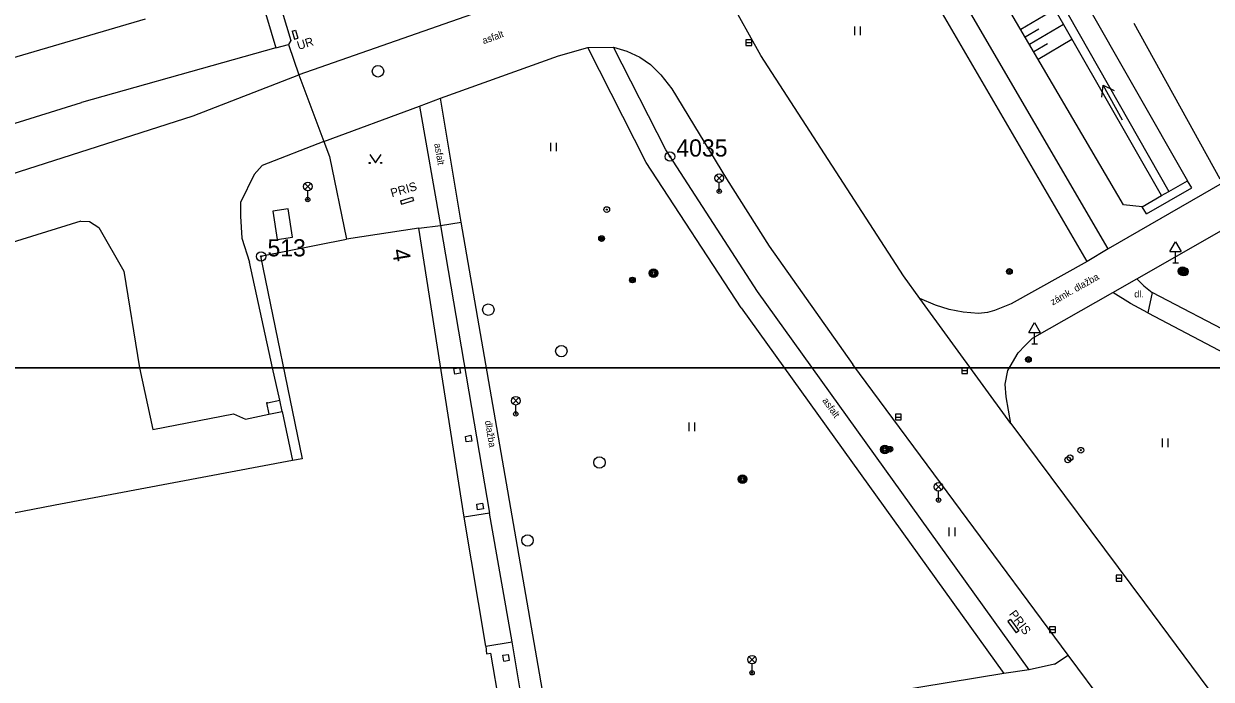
# Model space of a CAD drawing. Extents: x -493753 to -49290, y -1127285 to -112654.
# Drawn here: x -493511.1 to -493407.4, y -1127027.2 to -1126970 of the extents above; entities that cross this region are included whole.
import ezdxf

# ---------------------------------------------------------------- set-up
doc = ezdxf.new("R2010")
doc.units = 0
for name, color, linetype in [('Vrstva 10', 7, 'Continuous'), ('Vrstva 11', 7, 'Continuous'), ('Vrstva 14', 7, 'Continuous'), ('Vrstva 15', 7, 'Continuous'), ('Vrstva 24', 7, 'Continuous'), ('Vrstva 25', 7, 'Continuous'), ('Vrstva 27', 7, 'Continuous'), ('Vrstva 28', 7, 'Continuous'), ('Vrstva 31', 7, 'Continuous'), ('Vrstva 33', 7, 'Continuous'), ('Vrstva 34', 7, 'Continuous'), ('Vrstva 36', 7, 'Continuous'), ('Vrstva 40', 7, 'Continuous'), ('Vrstva 42', 7, 'Continuous'), ('Vrstva 44', 7, 'Continuous'), ('Vrstva 45', 7, 'Continuous'), ('Vrstva 5', 7, 'Continuous'), ('Vrstva 60', 7, 'Continuous'), ('Vrstva 63', 7, 'Continuous'), ('Vrstva 7', 7, 'Continuous'), ('Vrstva 8', 7, 'Continuous')]:
    doc.layers.add(name, color=color, linetype=linetype)

msp = doc.modelspace()

# ---------------------------------------------------------------- linework, layer by layer
at = {"layer": 'Vrstva 10'}
for p, q in [((-493416.42, -1126989.62), (-493448.94, -1126933.89)), ((-493418.27, -1126990.72), (-493451.01, -1126934.56)), ((-493446.75, -1126972.75), (-493453.23, -1126961.09)), ((-493464.93, -1126966.68), (-493487.06, -1126974.42)), ((-493464.41, -1126972.76), (-493461.84, -1126972.04)), ((-493461.84, -1126972.04), (-493459.59, -1126972.03)), ((-493456.75, -1126982.08), (-493461.84, -1126972.04)), ((-493455.02, -1126980.96), (-493459.59, -1126972.03)), ((-493474.71, -1126976.48), (-493464.41, -1126972.76)), ((-493434.29, -1126991.96), (-493446.75, -1126972.75)), ((-493454.52, -1126975.65), (-493449.75, -1126983.49)), ((-493476.53, -1126977.16), (-493474.71, -1126976.48)), ((-493472.89, -1126987.28), (-493474.71, -1126976.48)), ((-493484.89, -1126980.24), (-493476.53, -1126977.16)), ((-493476.53, -1126977.16), (-493474.69, -1126987.58)), ((-493447.03, -1126993.34), (-493455.02, -1126980.96)), ((-493448.45, -1126994.76), (-493456.75, -1126982.08)), ((-493449.75, -1126983.49), (-493446.02, -1126989.37)), ((-493406.46, -1126983.89), (-493416.42, -1126989.62)), ((-493409.13, -1126984.29), (-493409.5, -1126983.67)), ((-493413.09, -1126986.57), (-493409.13, -1126984.29)), ((-493413.09, -1126986.57), (-493413.46, -1126985.95)), ((-493413.91, -1126992.22), (-493404.75, -1126986.99)), ((-493464.92, -1127033.14), (-493472.89, -1126987.28)), ((-493446.02, -1126989.37), (-493438.7, -1126999.69)), ((-493418.27, -1126990.72), (-493424.88, -1126994.4)), ((-493432.85, -1126993.93), (-493434.29, -1126991.96)), ((-493423.31, -1127026.33), (-493447.03, -1126993.34)), ((-493424.93, -1127004.86), (-493432.85, -1126993.93)), ((-493423.04, -1126997.41), (-493416.01, -1126993.41)), ((-493391.92, -1127004.22), (-493412.57, -1126993.41)), ((-493448.45, -1126994.76), (-493425.54, -1127026.66)), ((-493412.95, -1126995.18), (-493392.82, -1127005.8)), ((-493473.53, -1127000.06), (-493473.04, -1126999.98)), ((-493473.45, -1127000.55), (-493473.53, -1127000.06)), ((-493472.95, -1127000.47), (-493473.45, -1127000.55)), ((-493473.04, -1126999.98), (-493472.95, -1127000.47)), ((-493419.91, -1127025.06), (-493438.7, -1126999.69)), ((-493424.93, -1127004.86), (-493413.25, -1127020.49)), ((-493472.53, -1127005.97), (-493472.04, -1127005.88)), ((-493472.45, -1127006.46), (-493472.53, -1127005.97)), ((-493471.96, -1127006.38), (-493472.45, -1127006.46)), ((-493472.04, -1127005.88), (-493471.96, -1127006.38)), ((-493471.54, -1127011.88), (-493471.05, -1127011.8)), ((-493471.46, -1127012.37), (-493471.54, -1127011.88)), ((-493471.05, -1127011.8), (-493470.96, -1127012.29)), ((-493470.96, -1127012.29), (-493471.46, -1127012.37)), ((-493468.45, -1127023.89), (-493470.41, -1127012.67)), ((-493469.26, -1127025.07), (-493468.76, -1127024.99)), ((-493469.18, -1127025.57), (-493469.26, -1127025.07)), ((-493469.18, -1127025.57), (-493468.69, -1127025.49)), ((-493468.69, -1127025.49), (-493468.76, -1127024.99)), ((-493421.12, -1127025.84), (-493419.91, -1127025.06)), ((-493411.78, -1127035.96), (-493419.91, -1127025.06)), ((-493423.31, -1127026.33), (-493425.54, -1127026.66)), ((-493421.12, -1127025.84), (-493423.31, -1127026.33))]:
    msp.add_line(p, q, dxfattribs=at)
for points in [[(-493459.59, -1126972.03), (-493458.45, -1126972.37), (-493457.31, -1126972.88), (-493456.37, -1126973.52), (-493455.47, -1126974.42), (-493454.52, -1126975.65)], [(-493413.46, -1126985.95), (-493411.76, -1126984.97), (-493411.12, -1126984.6), (-493409.5, -1126983.67)], [(-493413.91, -1126992.22), (-493413.32, -1126992.83), (-493412.57, -1126993.41)], [(-493427.75, -1126995.25), (-493429.09, -1126995.13), (-493430.29, -1126994.89), (-493431.48, -1126994.53), (-493432.85, -1126993.93)], [(-493424.88, -1126994.4), (-493426.35, -1126995), (-493426.97, -1126995.17), (-493427.75, -1126995.25)], [(-493412.95, -1126995.18), (-493414.47, -1126994.37), (-493416.01, -1126993.41)], [(-493425.19, -1127000.22), (-493424.27, -1126998.69), (-493423.67, -1126998.03), (-493423.04, -1126997.41)], [(-493424.93, -1127004.86), (-493425.33, -1127002.51), (-493425.41, -1127001.41), (-493425.19, -1127000.22)], [(-493413.25, -1127020.49), (-493403.62, -1127033.47)], [(-493425.54, -1127026.66), (-493464.92, -1127033.14), (-493466.83, -1127033.46)]]:
    msp.add_lwpolyline(points, dxfattribs=at)
at = {"layer": 'Vrstva 11'}
for p, q in [((-493474.69, -1126987.58), (-493472.89, -1126987.28)), ((-493416.42, -1126989.62), (-493418.27, -1126990.72)), ((-493416.01, -1126993.41), (-493413.91, -1126992.22)), ((-493412.57, -1126993.41), (-493412.95, -1126995.18))]:
    msp.add_line(p, q, dxfattribs=at)
for points in [[(-493524.38, -1126986.98), (-493496.3, -1126978.01), (-493487.06, -1126974.42)], [(-493536.04, -1126986.19), (-493506.03, -1126976.85)], [(-493484.89, -1126980.24), (-493490.28, -1126982.35), (-493490.98, -1126983.14), (-493492.16, -1126985.58), (-493492.16, -1126986.76), (-493492.03, -1126988.68), (-493491.36, -1126990.78)], [(-493488, -1126986.12), (-493489.33, -1126986.33)], [(-493489.33, -1126986.33), (-493488.95, -1126988.8)], [(-493487.62, -1126988.59), (-493488, -1126986.12)], [(-493506.09, -1126987.19), (-493523.25, -1126992.52)], [(-493506.09, -1126987.19), (-493505.35, -1126987.23), (-493504.52, -1126987.76), (-493502.34, -1126991.55), (-493500.98, -1127000)], [(-493488.95, -1126988.8), (-493487.62, -1126988.59)], [(-493489.36, -1127000), (-493491.36, -1126990.78)], [(-493500.98, -1127000), (-493499.8, -1127005.36), (-493492.77, -1127004.02), (-493491.71, -1127004.47), (-493489.69, -1127004.03)], [(-493488.74, -1127002.81), (-493489.36, -1127000)], [(-493489.81, -1127003.04), (-493489.9, -1127003.06)], [(-493489.9, -1127003.06), (-493489.69, -1127004.03)], [(-493489.81, -1127003.04), (-493488.74, -1127002.81)], [(-493488.53, -1127003.79), (-493488.74, -1127002.81)], [(-493489.69, -1127004.03), (-493488.53, -1127003.79)], [(-493488.53, -1127003.79), (-493487.63, -1127008.08)], [(-493487.63, -1127008.08), (-493508.33, -1127011.97)], [(-493486.79, -1127007.92), (-493487.63, -1127008.08)], [(-493508.33, -1127011.97), (-493523.38, -1127014.87)]]:
    msp.add_lwpolyline(points, dxfattribs=at)
at = {"layer": 'Vrstva 14'}
for p, q in [((-493441.57, -1126927.45), (-493409.5, -1126983.67)), ((-493411.76, -1126984.97), (-493444.16, -1126928.37)), ((-493443.13, -1126928.34), (-493411.12, -1126984.6)), ((-493415.09, -1126985.77), (-493447.31, -1126930.76)), ((-493413.46, -1126985.95), (-493415.09, -1126985.77))]:
    msp.add_line(p, q, dxfattribs=at)
at = {"layer": 'Vrstva 15'}
for p, q in [((-493424.06, -1126970.46), (-493421.07, -1126968.71)), ((-493423.68, -1126971.11), (-493422.48, -1126970.41)), ((-493423.3, -1126971.76), (-493420.32, -1126970.01)), ((-493422.54, -1126973.05), (-493419.58, -1126971.31)), ((-493422.92, -1126972.4), (-493421.73, -1126971.71))]:
    msp.add_line(p, q, dxfattribs=at)
at = {"layer": 'Vrstva 24'}
for p, q in [((-493487.66, -1126970.61), (-493487.37, -1126970.52)), ((-493487.37, -1126970.52), (-493487.15, -1126971.23)), ((-493487.66, -1126970.61), (-493487.44, -1126971.32)), ((-493487.44, -1126971.32), (-493487.15, -1126971.23)), ((-493478.18, -1126985.41), (-493477.15, -1126985.11)), ((-493478.18, -1126985.41), (-493478.1, -1126985.7)), ((-493478.1, -1126985.7), (-493477.07, -1126985.4)), ((-493477.15, -1126985.11), (-493477.07, -1126985.4)), ((-493424.95, -1127021.94), (-493425.19, -1127022.12)), ((-493425.19, -1127022.12), (-493424.45, -1127023.11)), ((-493424.95, -1127021.94), (-493424.21, -1127022.93)), ((-493424.21, -1127022.93), (-493424.45, -1127023.11))]:
    msp.add_line(p, q, dxfattribs=at)
at = {"layer": 'Vrstva 25'}
for centre, radius in [((-493460.19, -1126986.19), 0.25), ((-493460.19, -1126986.19), 0.05), ((-493460.64, -1126988.72), 0.25), ((-493460.64, -1126988.72), 0.158), ((-493460.64, -1126988.72), 0.05), ((-493457.95, -1126992.33), 0.25), ((-493457.95, -1126992.33), 0.158), ((-493457.95, -1126992.33), 0.05), ((-493425.04, -1126991.58), 0.25), ((-493425.04, -1126991.58), 0.158), ((-493425.04, -1126991.58), 0.05), ((-493423.38, -1126999.26), 0.25), ((-493423.38, -1126999.26), 0.158), ((-493423.38, -1126999.26), 0.05), ((-493435.48, -1127007.1), 0.25), ((-493435.48, -1127007.1), 0.158), ((-493435.48, -1127007.1), 0.05), ((-493418.81, -1127007.18), 0.25), ((-493418.81, -1127007.18), 0.05)]:
    msp.add_circle(centre, radius, dxfattribs=at)
at = {"layer": 'Vrstva 27'}
for p, q in [((-493448.04, -1126971.62), (-493447.54, -1126971.62)), ((-493429.19, -1127000.23), (-493428.69, -1127000.23)), ((-493434.98, -1127004.29), (-493434.48, -1127004.29)), ((-493415.73, -1127018.34), (-493415.23, -1127018.34)), ((-493421.53, -1127022.83), (-493421.03, -1127022.83))]:
    msp.add_line(p, q, dxfattribs=at)
for points in [[(-493448.04, -1126971.87), (-493447.54, -1126971.87), (-493447.54, -1126971.37), (-493448.04, -1126971.37)], [(-493429.19, -1127000.48), (-493428.69, -1127000.48), (-493428.69, -1126999.98), (-493429.19, -1126999.98)], [(-493434.98, -1127004.54), (-493434.48, -1127004.54), (-493434.48, -1127004.04), (-493434.98, -1127004.04)], [(-493415.73, -1127018.59), (-493415.23, -1127018.59), (-493415.23, -1127018.09), (-493415.73, -1127018.09)], [(-493421.53, -1127023.08), (-493421.03, -1127023.08), (-493421.03, -1127022.58), (-493421.53, -1127022.58)]]:
    msp.add_lwpolyline(points, close=True, dxfattribs=at)
for centre in [(-493480.16, -1126974.12), (-493470.53, -1126994.92), (-493464.15, -1126998.53), (-493460.83, -1127008.25), (-493467.1, -1127015.05)]:
    msp.add_circle(centre, 0.5, dxfattribs=at)
at = {"layer": 'Vrstva 28'}
for centre in [(-493419.95, -1127008.02), (-493419.75, -1127007.84)]:
    msp.add_circle(centre, 0.25, dxfattribs=at)
at = {"layer": 'Vrstva 31'}
for centre, radius in [((-493409.93, -1126991.55), 0.375), ((-493409.93, -1126991.55), 0.283), ((-493409.82, -1126991.6), 0.375), ((-493456.1, -1126991.73), 0.375), ((-493456.1, -1126991.73), 0.283), ((-493456.1, -1126991.73), 0.224), ((-493456.1, -1126991.73), 0.112), ((-493409.93, -1126991.55), 0.224), ((-493409.82, -1126991.6), 0.283), ((-493409.82, -1126991.6), 0.224), ((-493409.93, -1126991.55), 0.112), ((-493409.82, -1126991.6), 0.112), ((-493435.91, -1127007.12), 0.375), ((-493435.91, -1127007.12), 0.283), ((-493435.91, -1127007.12), 0.224), ((-493435.91, -1127007.12), 0.112), ((-493448.34, -1127009.71), 0.375), ((-493448.34, -1127009.71), 0.283), ((-493448.34, -1127009.71), 0.224), ((-493448.34, -1127009.71), 0.112)]:
    msp.add_circle(centre, radius, dxfattribs=at)
at = {"layer": 'Vrstva 33'}
for p, q in [((-493486.555, -1126983.905), (-493486.025, -1126984.435)), ((-493486.555, -1126984.435), (-493486.025, -1126983.905)), ((-493450.635, -1126983.175), (-493450.105, -1126983.705)), ((-493450.635, -1126983.705), (-493450.105, -1126983.175)), ((-493450.37, -1126984.59), (-493450.37, -1126983.815)), ((-493486.29, -1126985.32), (-493486.29, -1126984.545)), ((-493468.395, -1127002.595), (-493467.865, -1127003.125)), ((-493468.395, -1127003.125), (-493467.865, -1127002.595)), ((-493468.13, -1127004.01), (-493468.13, -1127003.235)), ((-493431.495, -1127010.115), (-493430.965, -1127010.645)), ((-493431.495, -1127010.645), (-493430.965, -1127010.115)), ((-493431.23, -1127011.53), (-493431.23, -1127010.755)), ((-493447.775, -1127025.185), (-493447.245, -1127025.715)), ((-493447.775, -1127025.715), (-493447.245, -1127025.185)), ((-493447.51, -1127026.6), (-493447.51, -1127025.825))]:
    msp.add_line(p, q, dxfattribs=at)
for centre, radius in [((-493486.29, -1126984.17), 0.375), ((-493450.37, -1126983.44), 0.375), ((-493450.37, -1126984.59), 0.19), ((-493450.37, -1126984.59), 0.05), ((-493486.29, -1126985.32), 0.19), ((-493486.29, -1126985.32), 0.05), ((-493468.13, -1127002.86), 0.375), ((-493468.13, -1127004.01), 0.19), ((-493468.13, -1127004.01), 0.05), ((-493431.23, -1127010.38), 0.375), ((-493431.23, -1127011.53), 0.19), ((-493431.23, -1127011.53), 0.05), ((-493447.51, -1127025.45), 0.375), ((-493447.51, -1127026.6), 0.19), ((-493447.51, -1127026.6), 0.05)]:
    msp.add_circle(centre, radius, dxfattribs=at)
at = {"layer": 'Vrstva 34'}
for p, q in [((-493411.04, -1126989.84), (-493410.54, -1126988.99)), ((-493410.54, -1126988.99), (-493410.04, -1126989.84)), ((-493411.04, -1126989.84), (-493410.04, -1126989.84)), ((-493410.54, -1126990.84), (-493410.54, -1126989.84)), ((-493410.79, -1126990.84), (-493410.29, -1126990.84)), ((-493423.35, -1126996.9), (-493422.85, -1126996.05)), ((-493422.85, -1126996.05), (-493422.35, -1126996.9)), ((-493423.35, -1126996.9), (-493422.35, -1126996.9)), ((-493422.85, -1126997.9), (-493422.85, -1126996.9)), ((-493423.1, -1126997.9), (-493422.6, -1126997.9))]:
    msp.add_line(p, q, dxfattribs=at)
at = {"layer": 'Vrstva 36'}
for p, q in [((-493438.53, -1126970.97), (-493438.53, -1126970.22)), ((-493438.03, -1126970.97), (-493438.03, -1126970.22)), ((-493465.08, -1126981.1), (-493465.08, -1126980.35)), ((-493464.58, -1126981.1), (-493464.58, -1126980.35)), ((-493480.88, -1126981.37), (-493480.38, -1126982.12)), ((-493480.38, -1126982.12), (-493479.88, -1126981.37)), ((-493453.01, -1127005.51), (-493453.01, -1127004.76)), ((-493452.51, -1127005.51), (-493452.51, -1127004.76)), ((-493411.68, -1127006.92), (-493411.68, -1127006.17)), ((-493411.18, -1127006.92), (-493411.18, -1127006.17)), ((-493430.29, -1127014.68), (-493430.29, -1127013.93)), ((-493429.79, -1127014.68), (-493429.79, -1127013.93))]:
    msp.add_line(p, q, dxfattribs=at)
for centre in [(-493480.88, -1126982.12), (-493479.88, -1126982.12)]:
    msp.add_circle(centre, 0.05, dxfattribs=at)
at = {"layer": 'Vrstva 45'}
for p, q in [((-493416.975, -1126976.391), (-493416.85, -1126975.33)), ((-493415.161, -1126978.395), (-493416.85, -1126975.33)), ((-493416.85, -1126975.33), (-493415.887, -1126975.792))]:
    msp.add_line(p, q, dxfattribs=at)
at = {"layer": 'Vrstva 5'}
for p, q in [((-493500.47, -1126969.56), (-493517.82, -1126974.66)), ((-493476.59, -1126987.82), (-493482.91, -1126988.76)), ((-493476.59, -1126987.82), (-493474.69, -1126987.58)), ((-493472.64, -1127013.02), (-493476.59, -1126987.82)), ((-493474.69, -1126987.58), (-493470.41, -1127012.67)), ((-493490.41, -1126990.25), (-493482.91, -1126988.76)), ((-493490.41, -1126990.25), (-493486.79, -1127007.92)), ((-493470.41, -1127012.67), (-493472.64, -1127013.02)), ((-493470.74, -1127024.28), (-493472.64, -1127013.02)), ((-493470.74, -1127024.28), (-493468.45, -1127023.89)), ((-493470.74, -1127024.28), (-493470.68, -1127024.95)), ((-493466.83, -1127033.46), (-493468.45, -1127023.89)), ((-493470.68, -1127024.95), (-493470.31, -1127024.89)), ((-493465.02, -1127056.09), (-493470.31, -1127024.89))]:
    msp.add_line(p, q, dxfattribs=at)
at = {"layer": 'Vrstva 60'}
for points in [[(-493659.148, -1127000), (-493125, -1127000), (-493125, -1126587.478)], [(-493125, -1127069.371), (-493125, -1127000), (-493659.148, -1127000)]]:
    msp.add_lwpolyline(points, dxfattribs=at)
at = {"layer": 'Vrstva 63'}
for centre, radius in [((-493454.67, -1126981.56), 0.412), ((-493454.67, -1126981.56), 0.05), ((-493490.36, -1126990.27), 0.412), ((-493490.36, -1126990.27), 0.05)]:
    msp.add_circle(centre, radius, dxfattribs=at)
at = {"layer": 'Vrstva 7'}
for p, q in [((-493504.54, -1126915.49), (-493487.76, -1126971.44)), ((-493505.48, -1126916.94), (-493489.08, -1126972.08)), ((-493406.66, -1126983.52), (-493414.15, -1126969.94)), ((-493487.76, -1126971.44), (-493487.96, -1126971.77)), ((-493487.96, -1126971.77), (-493487.06, -1126974.42)), ((-493492.8, -1126973.11), (-493506.03, -1126976.85)), ((-493484.4, -1126981.56), (-493482.91, -1126988.76))]:
    msp.add_line(p, q, dxfattribs=at)
for points in [[(-493489.08, -1126972.08), (-493492.8, -1126973.11)], [(-493489.08, -1126972.08), (-493487.96, -1126971.77)]]:
    msp.add_lwpolyline(points, dxfattribs=at)
at = {"layer": 'Vrstva 8'}
for p, q in [((-493487.06, -1126974.42), (-493484.89, -1126980.24)), ((-493484.89, -1126980.24), (-493484.4, -1126981.56))]:
    msp.add_line(p, q, dxfattribs=at)

# ---------------------------------------------------------------- texts
at = {"layer": 'Vrstva 40'}
for s, rotation, p in [('asfalt', 19.85795, (-493470.934, -1126971.76)), ('asfalt', 279.68067, (-493475.253, -1126980.441)), ('zámk. dlažba', 29.63944, (-493421.268, -1126994.563)), ('asfalt', 305.68522, (-493441.403, -1127002.86)), ('dlažba', 279.68067, (-493470.834, -1127004.637))]:
    msp.add_text(s, height=0.6, rotation=rotation, dxfattribs=at).set_placement(p)
msp.add_text('dl.', height=0.6, dxfattribs=at).set_placement((-493414.148, -1126993.85))
at = {"layer": 'Vrstva 42'}
for s, rotation, p in [('UR', 17.21607, (-493487.088, -1126972.265)), ('PRIS', 16.23884, (-493478.939, -1126985.124)), ('PRIS', 306.77719, (-493425.113, -1127021.48))]:
    msp.add_text(s, height=0.75, rotation=rotation, dxfattribs=at).set_placement(p)
at = {"layer": 'Vrstva 44'}
msp.add_text('4', height=1.5, rotation=279.65458, dxfattribs=at).set_placement((-493478.94, -1126989.715))
at = {"layer": 'Vrstva 63'}
for s, p in [(' 4035', (-493454.67, -1126981.56)), (' 513', (-493490.36, -1126990.27))]:
    msp.add_text(s, height=1.5, dxfattribs=at).set_placement(p)

doc.saveas('drawing.dxf')
